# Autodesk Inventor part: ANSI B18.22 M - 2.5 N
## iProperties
Comments: To add or edit properties for Autodesk Inventor files, use iProperties.
Created: 2004-07
Part Number: ANSI B18.22 M - 2.5 N
Vendor: Autodesk Inc.
Document SubType Name: Modeling
Designer: John Blackburn
Material: Default
Description: Plain Washer
Standard: ANSI B18.22 M
Alert: To add or edit properties for Autodesk Inventor files, use iProperties.
Control State: 0
Master: False
Checked Out: False
Shininess: 64.0
Length Units: 11269
Angle Units: 11279
Time Units: 11290
Mass Units: 11283
Length Display Precision: 3
Angle Display Precision: 2
Compacted: True
Classification: un/spsc 31161807
Density: 0.0
Volumn: 0.0
Area: 0.0
PropertySet Name: Model Information
Author: John Blackburn
Revision Number: 8
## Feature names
1. Body [Extrusion]
